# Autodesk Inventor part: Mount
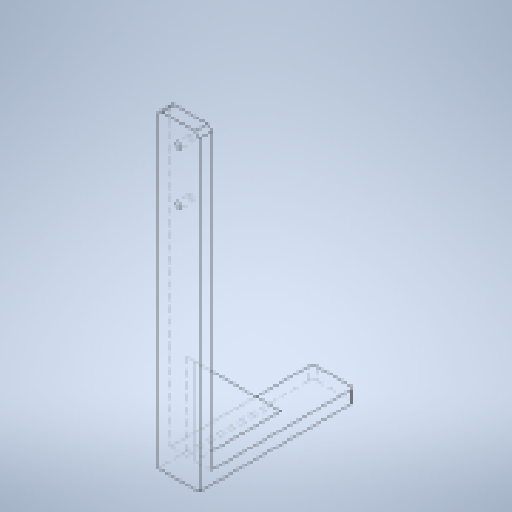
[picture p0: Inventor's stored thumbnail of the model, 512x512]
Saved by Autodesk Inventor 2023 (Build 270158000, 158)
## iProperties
Created: 2023-11
Part Number: Mount
Material: Generic
Document SubType Name: Modeling
Designer: tornqvih
Density: 1 g/cm^3
Appearance: Default
Mass: 302.029 g
Surface Area: 562.324 cm^2
Volume: 302.029 cm^3
Author: tornqvih
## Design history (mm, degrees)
sketch "Sketch1"
  geometry: L1 (300, -12)-(12, -12); L2 (12, -12)-(12, -150); L3 (12, -150)-(0, -150); L4 (0, -150)-(0, 0); L5 (0, 0)-(300, 0); L6 (300, 0)-(300, -12); 1 further point
  constraints: 12 end point, 5 perpendicular, 1 coincident, 1 horizontal
  dimensions: "d0" = 12 distance between parallel lines of L1 L5; "d1" = 12 distance between parallel lines of L4 L2; "d2" = 300 distance of L4.end L5.end; "d3" = 150 distance of L3.end L4.end
extrude "Extrusion1" new body sketch "Sketch1" stored distance "d4" = 40; taper "d5" = 0 deg
sketch "Sketch2"
  geometry: L1 (12, -12)-(300, -12) reference; L2 (95.103, -12)-(12, -95.103); L3 (12, -150)-(12, -12) reference; 1 further point
  constraints: 2 end point, 2 point on line
  dimensions: "d6" = 45 deg angle of L3 L2
feature "Rib1" sketch "Sketch2" dims "d7" = 1, "d8" = 8, "d9" = 0, "d10" = 0, "d11" = 1, "d12" = 1
sketch "Sketch3"
  geometry: L1 (0, 0)-(0, 300) reference; L2 (40, 300)-(0, 300) reference; 3 further points
  constraints: 1 vertical alignment
  dimensions: "d13" = 20 distance from line of L1 point (20, 280); "d14" = 20 distance from line of L2 point (20, 280); "d15" = 50 distance of point (20, 230) point (20, 280)
hole "Hole1" sketch "Sketch3" at (20, 280), (20, 230) diameter "d16" = 5.5; stored, may be unused: countersink angle "d20" = 90 deg, drill point angle "d22" = 118 deg; dims "d17" = 6, "d18" = 4, "d19" = 2, "d21" = 8.8
fillet "Fillet1" dims "d23" = 4
body "Solid1"
